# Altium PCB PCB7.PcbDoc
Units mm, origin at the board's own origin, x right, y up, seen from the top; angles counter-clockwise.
Board outline 25.65 x 26.8 mm, 2 copper layers (Top Layer, Bottom Layer); 9 components, 7 nets, 23 pads, 0 vias.
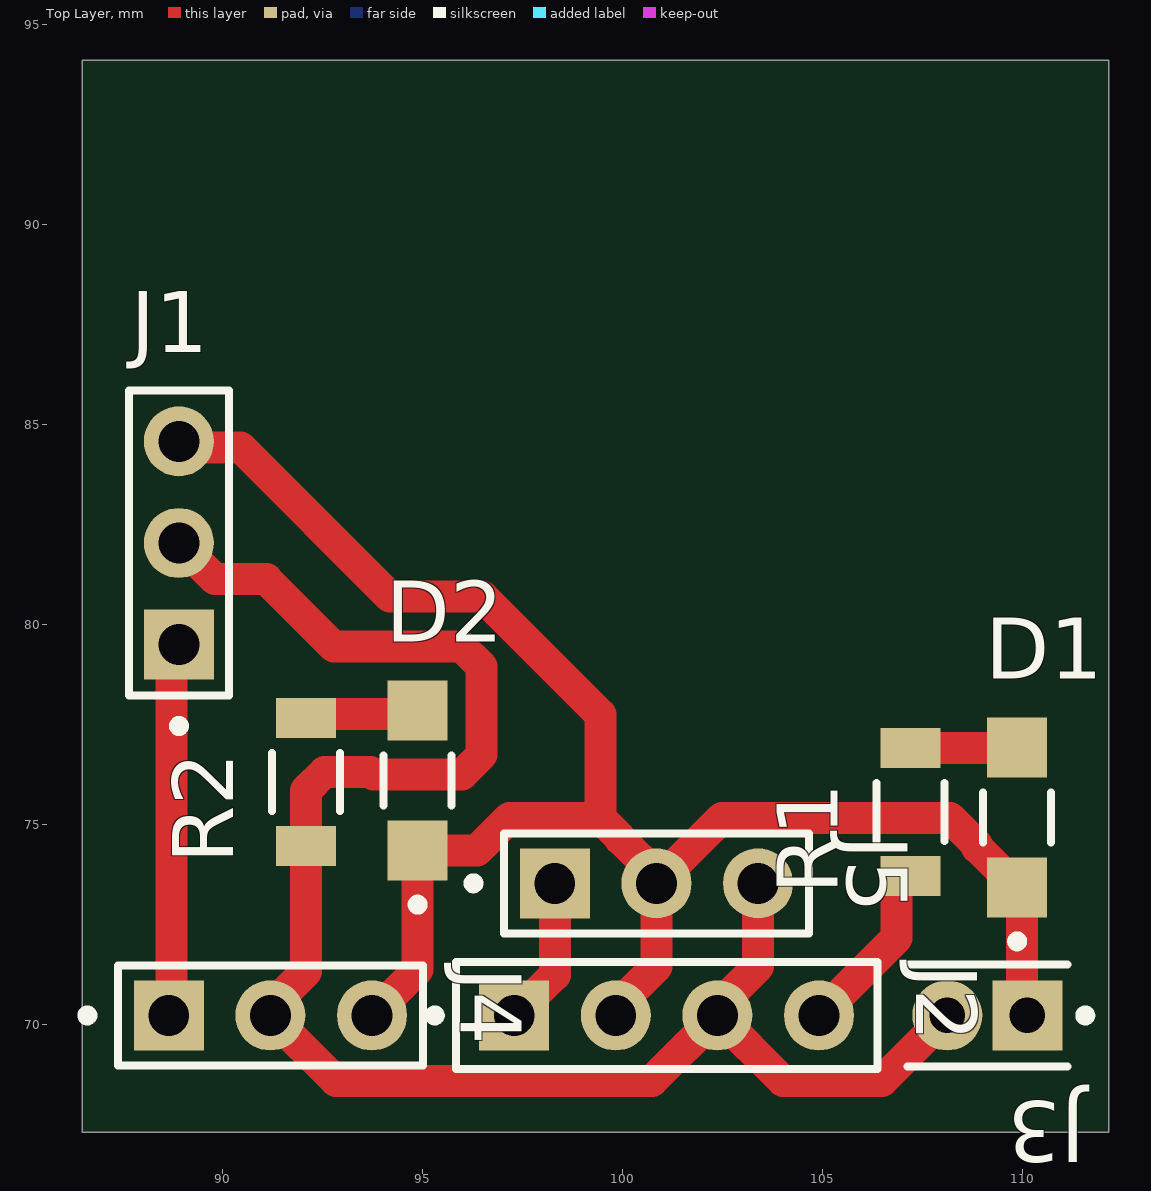
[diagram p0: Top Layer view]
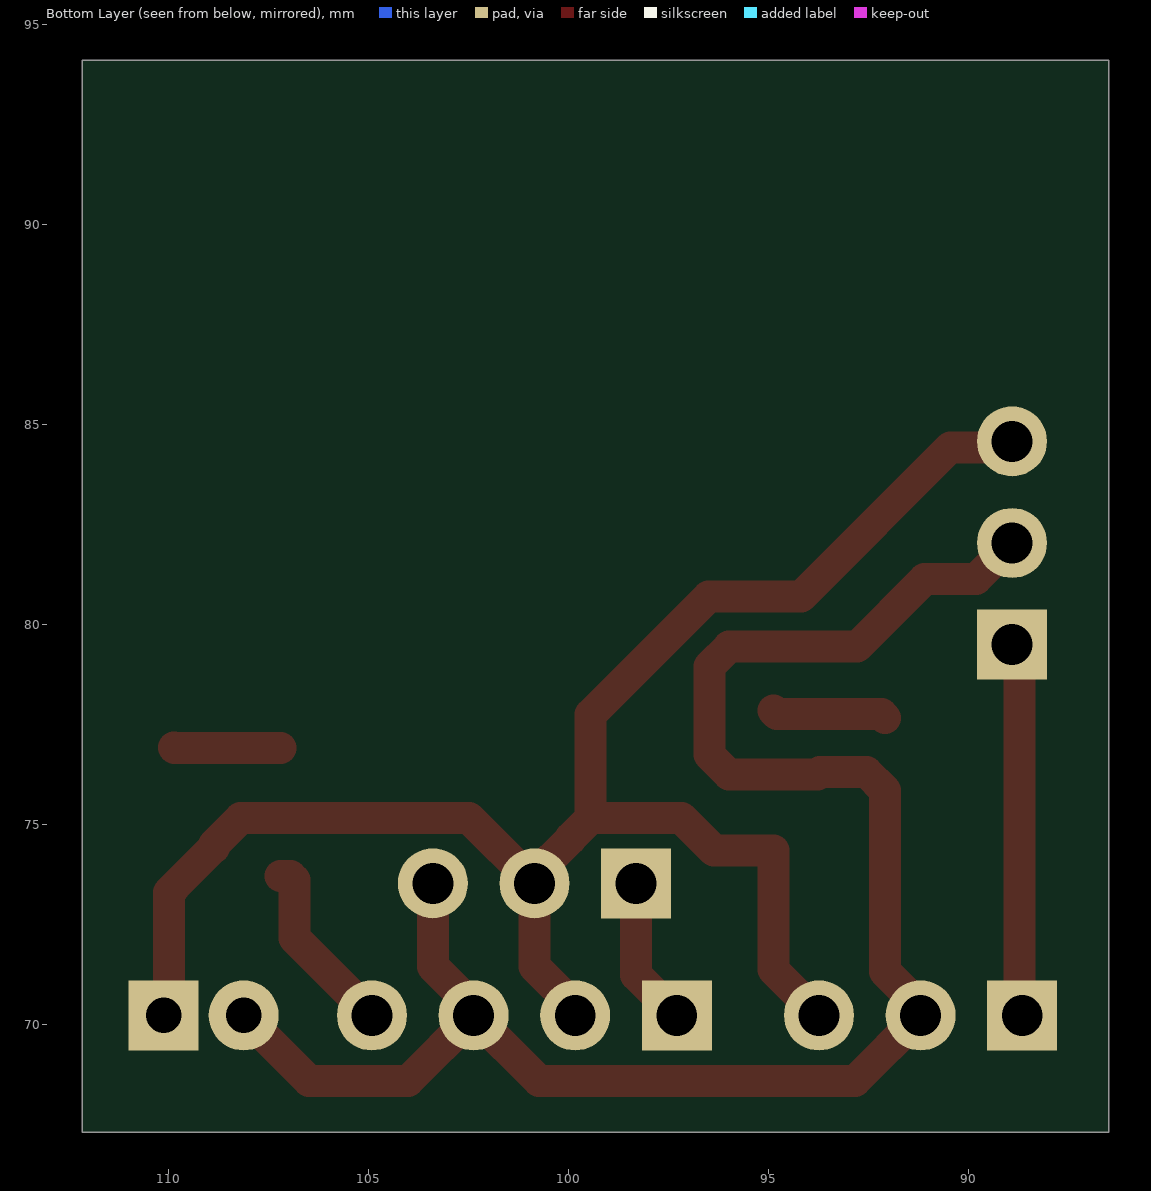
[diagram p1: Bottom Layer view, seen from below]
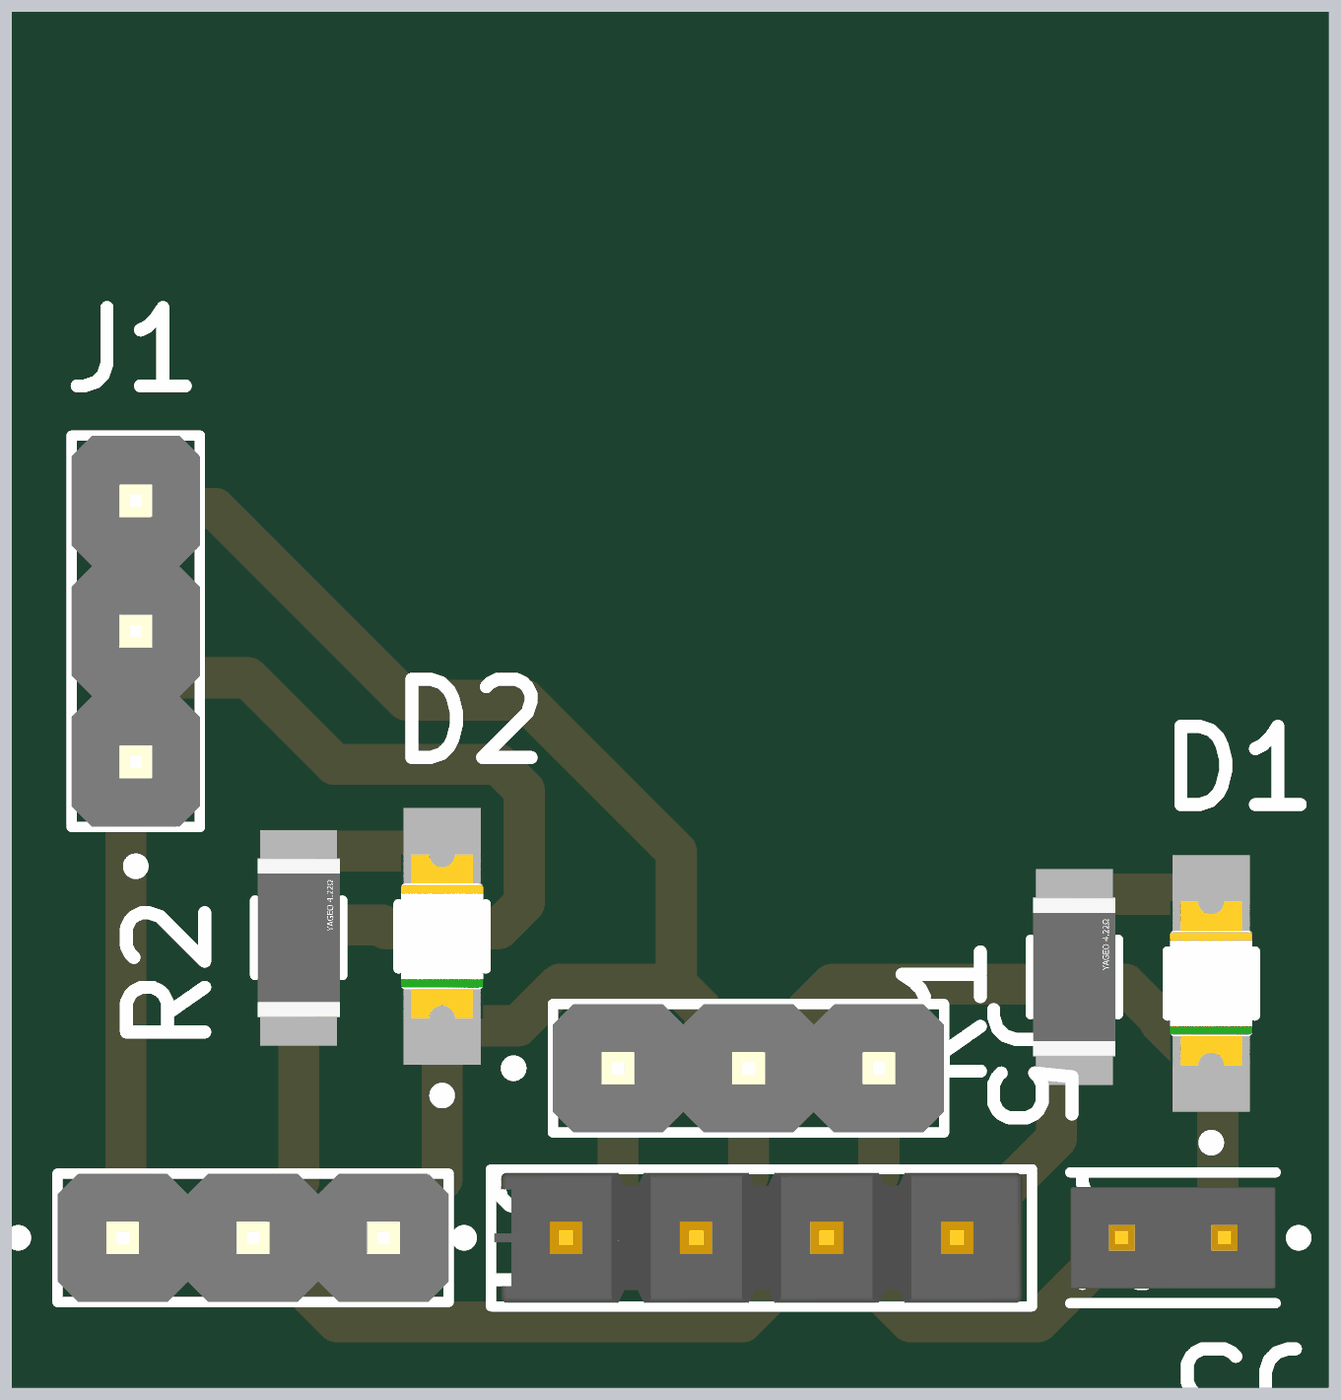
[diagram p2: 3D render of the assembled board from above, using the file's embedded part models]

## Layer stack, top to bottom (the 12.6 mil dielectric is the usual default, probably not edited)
Top Solder: solder mask 0.0102, Solder Resist, Dk 3.5
Top Layer: signal copper 0.0356
Dielectric 1: dielectric 0.32, FR-4, Dk 4.8
Bottom Layer: signal copper 0.0356
Bottom Solder: solder mask 0.0102, Solder Resist, Dk 3.5

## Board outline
86.487,67.31 86.487,94.107 112.141,94.107 112.141,67.31

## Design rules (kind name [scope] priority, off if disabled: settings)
Clearance [All] p1: gap=0.45 ignorepadtopadclearanceinfootprint=FALSE
PolygonConnect [All] p1: connectstyle=Relief reliefconductorwidth=0.254 reliefentries=4 polygonreliefangle="90 Angle" airgapwidth=0.254
RoutingVias [All] p1: holewidth=0.711 width=1.27 viastyle="Through Hole" minholewidth=0.711 minwidth=1.27 maxholewidth=0.711 maxwidth=1.27
SolderMaskExpansion [All] p1: expansion=0 istentingtop=FALSE
SupplyNets "Schematic Supply Nets" [InNet('GND')] p1: voltage=0.000
Width [All] p1: maxlimit=0.8 minlimit=0.254 preferedwidth=0.8 toplayer_minwidth=0.8 bottomlayer_maxwidth=0.254 bottomlayer_prefwidth=0.254 minimp=50.000000 maximp=50.000000 favimp=50.000000
30 further rules are at their usual default settings.

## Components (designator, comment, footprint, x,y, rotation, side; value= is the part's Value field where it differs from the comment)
D1 "LED_2" FP-LTST-C150KSKT-MFG 109.855,75.184 r90 top
D2 "LED" FP-LTST-C150KSKT-MFG 94.869,76.101 r90 top
J1 "MOTOR1" FP-PR20203VBNN-MFG 88.9,82.042 r90 top
J2 "MICRO1" FP-TSW-104-22-G-S-MFG 101.092,70.231 r0 top
J3 "POWER" FP-TMM-102-01-L-S-MFG 109.109,70.231 r180 top
J4 "MOTOR1" FP-PR20203VBNN-MFG 91.186,70.231 r0 top
J5 "MICRO1" FP-PR20203VBNN-MFG 100.838,73.533 r0 top
R1 "." FP-AC1206-MFG 107.188,75.311 r90 top value=2.21KΩ
R2 "." FP-AC1206-MFG 92.075,76.073 r90 top value=2.21KΩ

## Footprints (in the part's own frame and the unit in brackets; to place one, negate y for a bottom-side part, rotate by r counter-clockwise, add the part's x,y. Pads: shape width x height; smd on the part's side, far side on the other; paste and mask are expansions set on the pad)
FP-AC1206-MFG [mm]
  rect 1x1.5 smd paste+0 mask+0: 1(-1.6,0) 2(1.6,0)
  silkscreen extent -0.72,-0.85 0.72,0.85, body extent -2.2,-0.95 2.2,0.95, height 0.25
FP-LTST-C150KSKT-MFG [mm]
  rect 1.5x1.5 smd paste+0 mask+0: 1(-1.75,0) 2(1.75,0)
  silkscreen extent -3.22,-0.85 0.63,0.85, body extent -2.6,-0.95 2.6,0.95, height 0.25
FP-PR20203VBNN-MFG [mm]
  rect 1.75x1.75 hole 1.02 paste-2539.97 mask+0: 1(-2.54,0)
  round 1.75 hole 1.02 paste-2539.97 mask+0: 2(0,0) 3(2.54,0)
  silkscreen extent -4.7,-1.25 3.81,1.25, body extent -3.91,-1.35 3.91,1.35, height 0.25
FP-TMM-102-01-L-S-MFG [mm]
  rect 1.75x1.75 hole 0.89 paste-2539.97 mask+0: 1(-1,0)
  round 1.75 hole 0.89 paste-2539.97 mask+0: 2(1,0)
  silkscreen extent -2.58,-1.28 2,1.28, body extent -2.1,-1.15 2.1,1.15, height 0.25
FP-TSW-104-22-G-S-MFG [mm]
  rect 1.75x1.75 hole 1.02 paste-2539.97 mask+0: 1(-3.81,0)
  round 1.75 hole 1.02 paste-2539.97 mask+0: 2(-1.27,0) 3(1.27,0) 4(3.81,0)
  silkscreen extent -5.92,-1.34 5.27,1.34, body extent -5.37,-1.44 5.37,1.44, height 0.25

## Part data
D1 D2: library part CMP-2000-06618-2, "LED YELLOW CLEAR 1206 SMD", Case Code (Imperial)=1206, Case Code (Metric)=3216, Color=Yellow, Forward Current=30mA, Forward Voltage=2.4V, Lens Color=Colorless, Max Operating Temperature=85°C, Min Operating Temperature=-55°C, Package Quantity=1, Power Dissipation=75mW, Reverse Voltage=5V, Test Current=20mA
J1 J4 J5: library part CMP-77940-000002-1, "CONN HEADER VERT 3POS 2.54MM", Current Rating=3A, Manufacturer="Metz Connect", Manufacturer Part Number=PR20203VBNN, Temperature="-40°C to +105°C", Temperature Range High=+105°C, Temperature Range Low=-40°C
J2: library part CMP-02766-001236-1, "CONN HEADER VERT 4POS 2.54MM"
J3: library part CMP-02766-001606-1, "CONN HEADER VERT 2POS 2MM", Housing Color=Black, Max Current Rating=3.9A, Max Operating Temperature=125°C, Max Voltage Rating (AC)=500V, Min Operating Temperature=-55°C
R1 R2: library part CMP-03412-032679-1, "RES SMD 2.21K OHM 1% 1/4W 1206", Manufacturer=Yageo, Manufacturer Part Number=AC1206FR-072K21L, Package=AC1206, Power Rating=0.25W, Resistance=2.21KΩ, Temperature="-55°C to +155°C", Temperature Range High=+155°C, Temperature Range Low=-55°C, Tolerance=0.01, Voltage Rating=200V

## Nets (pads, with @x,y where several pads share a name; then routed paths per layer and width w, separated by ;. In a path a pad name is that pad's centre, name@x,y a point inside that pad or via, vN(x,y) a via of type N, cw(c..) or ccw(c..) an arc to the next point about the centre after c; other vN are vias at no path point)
3V3: J1.2 J2.3 J3.2 J4.2 J5.3 R2.1 | length 45.4
  Top Layer w0.8: J1.2@88.796,82.146 89.805,81.137 91.085,81.137 92.771,79.451 93.767,79.451 95.971,79.451 96.469,78.953 96.469,76.749 95.971,76.251 93.767,76.251 93.695,76.323 92.544,76.323 92.075,75.854 R2.1 92.075,71.328 91.186,70.439 J4.2 92.821,68.596 100.727,68.596 J2.3 ; J5.3 103.378,71.455 102.362,70.439 J2.3 ; J3.2 106.474,68.596 103.997,68.596 J2.3
A0: J2.1 J5.1 | length 3.7
  Top Layer w0.8: J2.1 98.298,71.247 J5.1
D8: J1.1 J4.1 | length 9.3
  Top Layer w0.8: J4.1 88.709,70.294 J1.1@88.709,79.502
D10: J2.4 R1.1 | length 4.6
  Top Layer w0.8: J2.4 106.838,72.167 106.838,73.611 106.938,73.711 R1.1
GND: D1.1 D2.1 J1.3 J2.2 J3.1 J4.3 J5.2 | length 45.1
  Top Layer w0.8: J1.3 89.047,84.435 90.444,84.435 94.178,80.701 96.489,80.701 99.435,77.755 99.435,75.168 ; J4.3 94.869,71.374 D2.1 94.875,74.357 96.35,74.357 97.161,75.168 99.435,75.168 ; J2.2 99.822,70.439 100.838,71.455 J5.2 ; J3.1 109.982,70.358 109.982,73.307 D1.1 108.856,74.433 108.856,74.495 108.183,75.168 102.473,75.168 J5.2 ; 99.435,75.168 99.933,74.67 99.933,74.646 100.838,73.741 J5.2
NetD1_2: D1.2 R1.2 | length 2.7
  Top Layer w0.8: R1.2 107.199,76.922 109.843,76.922 D1.2
NetD2_2: D2.2 R2.2 | length 2.9
  Top Layer w0.8: R2.2 92.164,77.762 94.78,77.762 D2.2

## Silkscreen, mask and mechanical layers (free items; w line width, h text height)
Mechanical 1:
  the board outline again, w1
